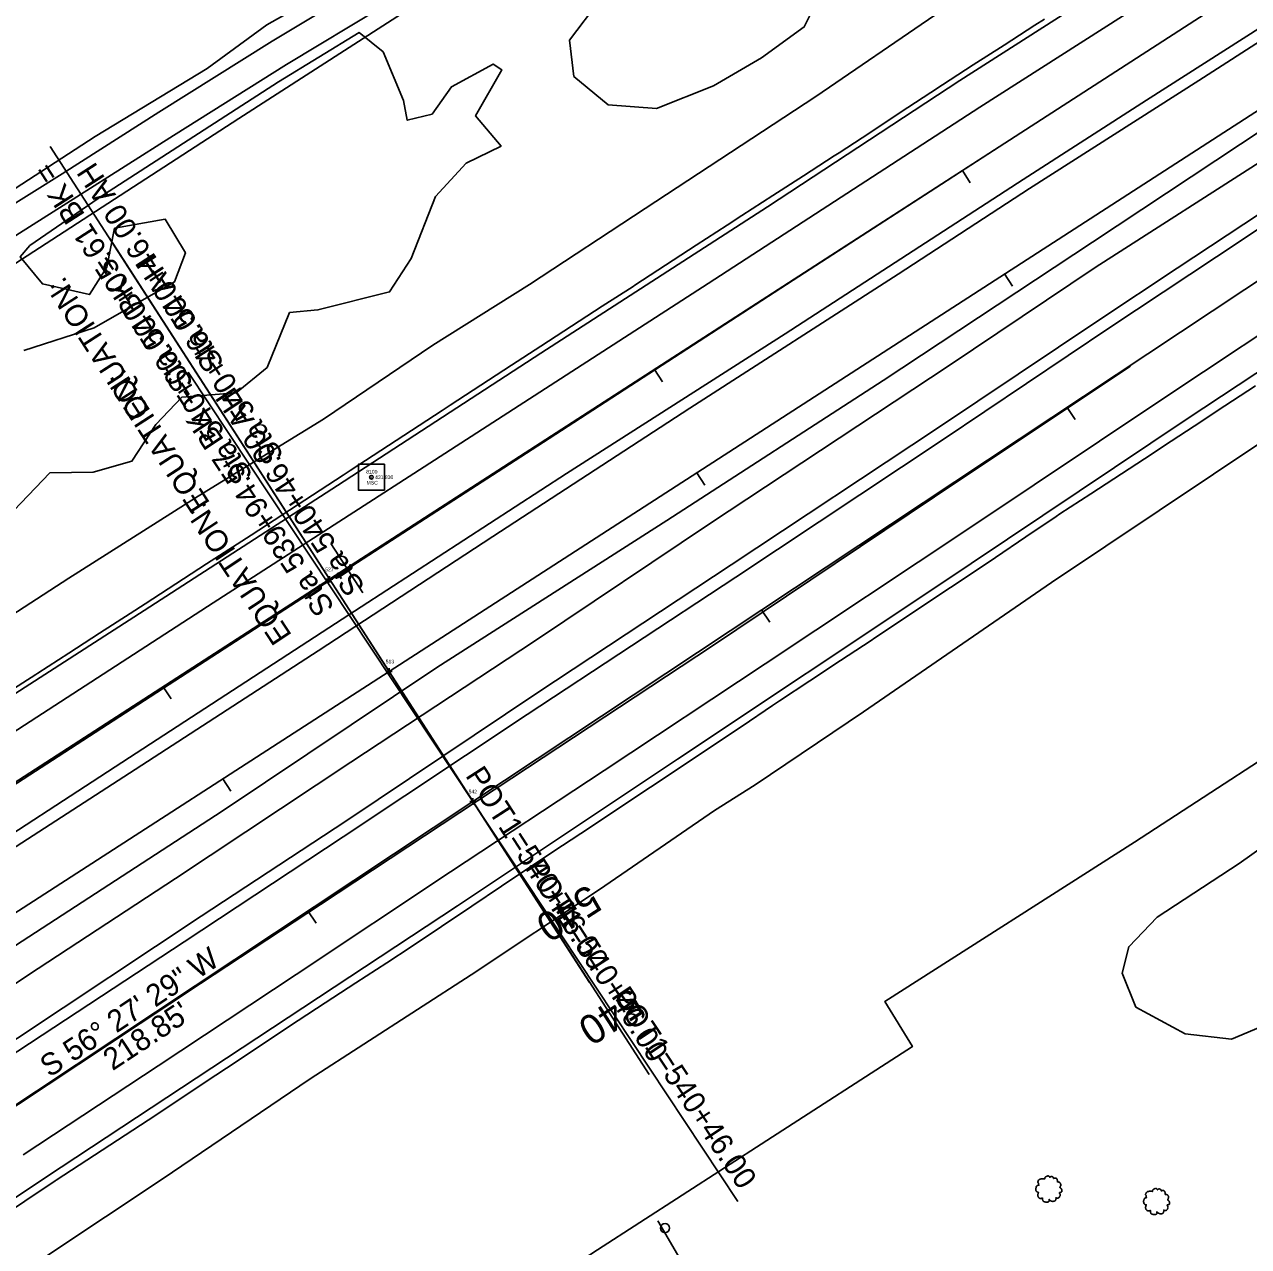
# Model space of a CAD drawing. Extents: x 1901471 to 1963503, y 756461 to 799997.
# Drawn here: x 1926646.3 to 1926980.4, y 771313.9 to 771647.3 of the extents above; entities that cross this region are included whole.
import ezdxf

# ---------------------------------------------------------------- set-up
doc = ezdxf.new("R2010")
doc.units = 0
for name, color, linetype in [('Default', 7, 'Continuous'), ('RD_DTM_BkLn1', 7, 'Continuous'), ('RD_EX_Bldg', 7, 'Continuous'), ('RD_EX_Conc', 7, 'Continuous'), ('RD_EX_Fence_Other', 7, 'Continuous'), ('RD_EX_H2O', 7, 'Continuous'), ('RD_EX_Road', 7, 'Continuous'), ('RD_EX_Road_txCode', 7, 'Continuous'), ('RD_EX_VEG', 7, 'Continuous'), ('RD_HC_Cl', 7, 'Continuous'), ('RD_HC_Data', 7, 'Continuous'), ('RD_HC_Data_Tic', 7, 'Continuous'), ('RD_HC_Survey', 7, 'Continuous'), ('RD_HC_TX_Sta50', 7, 'Continuous'), ('RD_HC_txCode', 7, 'Continuous'), ('RD_SMD_Locator', 7, 'Continuous')]:
    doc.layers.add(name, color=color, linetype=linetype)

# ---------------------------------------------------------------- blocks, each defined once
blk = doc.blocks.new('T2')
at = {"layer": 'RD_EX_VEG'}
for points in [[(0.05, 7.21), (-0.25, 7.24), (-0.57, 7.14), (-0.82, 7.04), (-1.05, 6.96), (-1.27, 6.86), (-1.57, 6.69), (-1.8, 6.49), (-1.92, 6.24), (-1.97, 6.01), (-2.02, 5.74), (-2.02, 5.56), (-2.15, 5.54), (-2.3, 5.56), (-2.55, 5.64), (-2.8, 5.64), (-3.05, 5.64), (-3.4, 5.61), (-3.75, 5.61), (-4.02, 5.56), (-4.35, 5.51), (-4.72, 5.39), (-5.07, 5.26), (-5.37, 5.01), (-5.62, 4.54), (-5.75, 4.19), (-5.9, 3.94), (-5.75, 3.49), (-5.57, 3.14), (-5.55, 2.94), (-5.47, 2.52), (-5.37, 2.29), (-5.25, 2.09), (-5.32, 2.07), (-5.7, 2.02), (-6, 1.92), (-6.42, 1.69), (-6.64, 1.47), (-6.74, 1.14), (-6.77, 0.79), (-6.87, 0.59), (-6.94, 0.32), (-6.97, 0.24), (-7.02, -0.08), (-6.92, -0.53), (-6.89, -0.88), (-6.77, -1.11), (-6.62, -1.28), (-6.44, -1.53), (-6.05, -1.76), (-5.72, -1.86), (-5.52, -1.88), (-5.7, -2.38), (-5.75, -2.73), (-5.87, -3.13), (-5.87, -3.21), (-5.92, -3.68), (-5.77, -4.01), (-5.7, -4.38), (-5.52, -4.61), (-5.25, -4.91), (-4.92, -5.13), (-4.42, -5.26), (-4.02, -5.23), (-3.45, -5.06), (-3.2, -4.98), (-3.22, -5.16), (-3.2, -5.53), (-3.2, -5.96), (-3.05, -6.28), (-2.95, -6.56), (-2.8, -6.81), (-2.47, -7.03), (-2.07, -7.11), (-1.65, -7.26), (-1.2, -7.33), (-0.7, -7.36), (-0.1, -7.21), (0.18, -7.08), (0.28, -6.91), (0.48, -6.53), (0.43, -6.31), (0.45, -5.71), (0.55, -5.88), (0.73, -6.23), (1.23, -6.53), (1.63, -6.71), (2.1, -6.86), (2.4, -6.93), (2.88, -6.86), (3.25, -6.78), (3.63, -6.66), (3.93, -6.38), (4.1, -6.11), (4.15, -5.83), (4.23, -5.46), (4.28, -5.28)], [(4.28, -5.28), (4.2, -5.11), (4.15, -4.86), (4.23, -4.88), (4.4, -4.93), (4.68, -5.06), (4.9, -5.13), (5.23, -5.11), (5.5, -5.01), (5.95, -4.73), (6.22, -4.26), (6.5, -3.86), (6.57, -3.53), (6.52, -3.31), (6.5, -2.81), (6.3, -2.56), (6.25, -2.43), (6.15, -2.03), (6.22, -1.98), (6.5, -1.93), (6.87, -1.81), (7.15, -1.68), (7.37, -1.51), (7.45, -1.28), (7.42, -0.88), (7.47, -0.48), (7.4, -0.33), (7.3, -0.18), (7.22, 0.02), (7.07, 0.17), (6.97, 0.32), (6.87, 0.42), (6.75, 0.57), (6.57, 0.69), (6.42, 0.74), (6.37, 0.89), (6.52, 1.09), (6.57, 1.19), (6.6, 1.42), (6.82, 1.77), (6.87, 2.17), (6.82, 2.59), (6.77, 2.87), (6.62, 3.14), (6.42, 3.39), (6.3, 3.56), (6.12, 3.69), (5.8, 3.81), (5.55, 3.86), (5.2, 3.86), (5, 3.91), (5.03, 3.96), (5.03, 4.11), (5.03, 4.39), (4.95, 4.84), (4.8, 5.34), (4.8, 5.36), (4.7, 5.61), (4.48, 5.81), (4.3, 5.91), (4.1, 6.04), (3.85, 6.06), (3.55, 6.06), (3.28, 6.01), (3.08, 5.91), (2.9, 5.79), (2.83, 5.94), (2.73, 6.24), (2.68, 6.39), (2.53, 6.56), (2.3, 6.76), (1.85, 6.89), (1.23, 6.81), (0.93, 6.61), (0.78, 6.44), (0.73, 6.56), (0.53, 6.76), (0.43, 6.94), (0.25, 7.06), (0.1, 7.16), (0, 7.21)]]:
    blk.add_spline(points, degree=3, dxfattribs=at)
blk = doc.blocks.new('SIGNPOST')
at = {"layer": 'Default'}
for start, end in [(90, 270), (270, 90)]:
    blk.add_arc((0, 0), 0.127, start, end, dxfattribs=at)

msp = doc.modelspace()

# ---------------------------------------------------------------- linework, layer by layer
at = {"layer": 'Default'}
for p, q in [((1926730.39, 771495.93), (1926728.64, 771495.93)), ((1926729.52, 771496.8), (1926729.52, 771495.05)), ((1926746.63, 771470.78), (1926744.88, 771470.78)), ((1926745.76, 771471.65), (1926745.76, 771469.9)), ((1926768.65, 771436.19), (1926768.65, 771434.44)), ((1926769.53, 771435.31), (1926767.78, 771435.31))]:
    msp.add_line(p, q, dxfattribs=at)
at = {"layer": 'RD_DTM_BkLn1'}
for points in [[(1926640.96, 771464.62), (1926649.39, 771470), (1926649.94, 771470.36), (1926658.34, 771475.78), (1926666.75, 771481.2), (1926675.15, 771486.63), (1926679.18, 771489.23), (1926687.57, 771494.67), (1926695.96, 771500.12), (1926704.35, 771505.56), (1926708.14, 771508.01), (1926716.52, 771513.47), (1926724.9, 771518.92), (1926733.28, 771524.38), (1926735.15, 771525.59), (1926743.51, 771531.07), (1926751.88, 771536.54), (1926760.25, 771542.01), (1926762.42, 771543.43), (1926770.81, 771548.88), (1926779.19, 771554.33), (1926787.19, 771559.53), (1926795.58, 771564.98), (1926803.97, 771570.42), (1926812.36, 771575.86), (1926812.87, 771576.19), (1926821.26, 771581.64), (1926829.64, 771587.09), (1926838.02, 771592.54), (1926842.08, 771595.18), (1926850.49, 771600.6), (1926858.9, 771606.01), (1926867.3, 771611.43), (1926868.62, 771612.27), (1926876.97, 771617.78), (1926885.32, 771623.28), (1926893.67, 771628.78), (1926896.82, 771630.86), (1926905.23, 771636.27), (1926913.64, 771641.68), (1926922.05, 771647.09), (1926924.7, 771648.79)], [(1926638.05, 771320.73), (1926646.36, 771326.29), (1926654.67, 771331.85), (1926654.93, 771332.03), (1926663.31, 771337.49), (1926671.68, 771342.96), (1926680.06, 771348.42), (1926681.8, 771349.56), (1926690.13, 771355.09), (1926698.45, 771360.63), (1926704.29, 771364.5), (1926712.63, 771370.02), (1926720.97, 771375.53), (1926728.35, 771380.4), (1926736.74, 771385.85), (1926745.13, 771391.3), (1926751.8, 771395.63), (1926760.1, 771401.21), (1926768.41, 771406.78), (1926776.45, 771412.18), (1926784.77, 771417.72), (1926793.09, 771423.27), (1926800.45, 771428.17), (1926808.79, 771433.69), (1926817.13, 771439.22), (1926825.51, 771444.77), (1926833.82, 771450.34), (1926842.12, 771455.91), (1926850.43, 771461.48), (1926852.31, 771462.74), (1926860.65, 771468.25), (1926868.99, 771473.76), (1926877.34, 771479.28), (1926878.4, 771479.98), (1926886.73, 771485.51), (1926895.06, 771491.04), (1926903, 771496.32), (1926911.29, 771501.91), (1926919.59, 771507.5), (1926927.88, 771513.09), (1926928.9, 771513.78), (1926937.28, 771519.24), (1926945.66, 771524.7), (1926954.04, 771530.16), (1926957.2, 771532.22), (1926965.54, 771537.73), (1926973.89, 771543.24), (1926982.23, 771548.75)]]:
    msp.add_lwpolyline(points, dxfattribs=at)
at = {"layer": 'RD_EX_Bldg'}
msp.add_lwpolyline([(1926819.14, 771320.9), (1926843.13, 771279.78)], dxfattribs=at)
at = {"layer": 'RD_EX_Conc'}
for points in [[(1926913.86, 771614.96), (1926856.12, 771577.52), (1926789.49, 771534.35), (1926717.34, 771487.72), (1926653.86, 771446.58), (1926587.5, 771403.7), (1926520.58, 771360.56), (1926450.82, 771315.78), (1926386.48, 771274.03), (1926337.64, 771242.68)], [(1926948.19, 771554.09), (1926901.28, 771522.85), (1926834.08, 771477.82), (1926779.24, 771441.71), (1926727.03, 771407.22), (1926694.32, 771385.69), (1926636.12, 771347.16), (1926575.7, 771307.03), (1926508.61, 771262.66), (1926440.97, 771217.97), (1926376.41, 771175.44)]]:
    msp.add_lwpolyline(points, dxfattribs=at)
at = {"layer": 'RD_EX_Fence_Other'}
for points in [[(1926123.55, 771248.7), (1926275.46, 771344.86), (1926355.52, 771395.91), (1926424.79, 771441.17), (1926530.89, 771509.43), (1926628.27, 771572.09), (1926704.79, 771621.63), (1926787.18, 771674.72), (1926849.91, 771715.16), (1926941.17, 771774.91), (1927014.76, 771822.08), (1927102.81, 771879.34), (1927189.76, 771936.16), (1927324.36, 772022.72), (1927401.87, 772072.57), (1927505.46, 772139.07), (1927552.57, 772169.38), (1927610.42, 772206.83), (1927669.56, 772245.41), (1927727.77, 772282), (1927850.35, 772361.69), (1927906.61, 772393.18), (1928159.93, 772541.58)], [(1926182.3, 771080.62), (1926247.6, 771123.86), (1926313.93, 771167.94), (1926371.02, 771205.25), (1926416.83, 771235.47), (1926477.89, 771275.65), (1926522.02, 771304.72), (1926569.04, 771335.92), (1926611.21, 771363.72), (1926647.32, 771388), (1926687.51, 771414.32), (1926735.3, 771446.06), (1926785.74, 771479.26), (1926833.51, 771511.22), (1926898.65, 771554.27), (1926938.55, 771580.97), (1926986.82, 771611.93), (1927022.76, 771635.27), (1927060.7, 771659.72), (1927104.19, 771687.49), (1927151.86, 771719.24), (1927193.2, 771746.24), (1927158.07, 771727.8)], [(1927228.56, 771605.61), (1927165.98, 771565.13), (1927099.93, 771522.87), (1927038.81, 771482.69), (1927005.75, 771461), (1926949.23, 771424.25), (1926881.07, 771380.73), (1926888.61, 771368.43), (1926848.87, 771342.84), (1926802.71, 771313), (1926719.32, 771258.75), (1926644.18, 771208.93), (1926569.77, 771160.02), (1926501.11, 771115.2), (1926445.81, 771078.5), (1926373.01, 771031.13), (1926312.17, 770989.89), (1926284.96, 770971.08)]]:
    msp.add_lwpolyline(points, dxfattribs=at)
at = {"layer": 'RD_EX_H2O'}
for points in [[(1926621.74, 771472.5), (1926658.38, 771496.29), (1926693.65, 771518.59), (1926727.86, 771539.59), (1926757.76, 771559.85), (1926784.12, 771576.35), (1926815.7, 771597.13), (1926862.25, 771627.63), (1926894.71, 771649.8), (1926905.89, 771656.34), (1926923.69, 771667.88), (1926953.22, 771687.95), (1926979.12, 771704.75), (1927005.16, 771721.72), (1927025.82, 771736.39), (1927046.28, 771750.15), (1927056.44, 771759.51)], [(1927178.55, 771746.03), (1927142.04, 771722.6), (1927087.07, 771685.87), (1927035.71, 771652.42), (1926984.95, 771619.06), (1926937.79, 771587.95), (1926880.68, 771550.21), (1926821.56, 771511.96), (1926758.84, 771471.9), (1926700.21, 771432.66), (1926643.77, 771396.01), (1926572.34, 771349.32), (1926498.61, 771301.78), (1926441.76, 771263.88), (1926366.72, 771215.15), (1926345.97, 771201.99), (1926308.41, 771177.14), (1926262.44, 771147.1)], [(1926411.81, 771116.97), (1926438.8, 771138.98), (1926480.42, 771170.67), (1926521.51, 771204.87), (1926537.81, 771219.83), (1926569.72, 771245.95), (1926601.52, 771273.26), (1926624.78, 771291.39), (1926652.88, 771311.72), (1926683.86, 771332.27), (1926724.26, 771359.64), (1926768.21, 771388), (1926803.18, 771411.27), (1926834.57, 771432.84), (1926845.7, 771439.87), (1926875.28, 771459.74), (1926926.55, 771495.04), (1926970.79, 771524.6), (1927006.19, 771548.26), (1927043.02, 771572.6), (1927072.89, 771592.2), (1927106.12, 771613.29), (1927137.2, 771633.31), (1927158.83, 771647.13)]]:
    msp.add_lwpolyline(points, dxfattribs=at)
at = {"layer": 'RD_EX_Road'}
for points in [[(1927002.69, 771834.44), (1926969.23, 771813.34), (1926939.87, 771793.11), (1926911.84, 771773.82), (1926879.83, 771751.75), (1926845.39, 771727.24), (1926813.48, 771704.98), (1926791.52, 771689.64), (1926764.88, 771673.54), (1926740.22, 771658.67), (1926713.82, 771642.74), (1926682.97, 771623.37), (1926656.55, 771606.59), (1926631.63, 771590.96)], [(1927006.64, 771828.07), (1926973.36, 771807.08), (1926944.13, 771786.94), (1926916.09, 771767.64), (1926884.14, 771745.61), (1926849.71, 771721.11), (1926817.77, 771698.83), (1926795.61, 771683.35), (1926768.75, 771667.11), (1926744.09, 771652.25), (1926717.75, 771636.36), (1926686.97, 771617.03), (1926660.56, 771600.25), (1926635.58, 771584.58)], [(1927167.58, 771805.44), (1927132.53, 771782.19), (1927125.25, 771776.81), (1927087.59, 771752.02), (1927053.76, 771729.63), (1927035.3, 771718.19), (1927013.38, 771703.59), (1926986.15, 771685.9), (1926961.73, 771670.26), (1926935.01, 771653.41), (1926901.57, 771632.05), (1926849.07, 771597.53), (1926787.19, 771557.66), (1926731.73, 771521.52), (1926678.93, 771487.39), (1926612.37, 771444.56), (1926561.87, 771411.9), (1926510.4, 771379.07), (1926470.49, 771353.37), (1926426.89, 771325.32), (1926388.11, 771299.87), (1926326.45, 771259.81), (1926252.5, 771212.2), (1926204.25, 771180.69)], [(1927149.35, 771780.93), (1927120.56, 771762.29), (1927086.84, 771740.15), (1927051.47, 771717.13), (1927018.6, 771696.09), (1926983.47, 771673.66), (1926945.99, 771649.59), (1926906.99, 771624.78), (1926832.84, 771576.62), (1926755.38, 771526.66), (1926697.72, 771489.54), (1926627.78, 771444.21), (1926557.1, 771398.6), (1926503.29, 771363.85), (1926451.94, 771330.76), (1926402.89, 771299.02), (1926358.62, 771270.33), (1926331.71, 771252.84), (1926280.14, 771219.61), (1926220.65, 771181.12), (1926155.39, 771139.06)], [(1926198.04, 771135.51), (1926265.67, 771178.91), (1926344.33, 771229.73), (1926401.98, 771266.94), (1926443.51, 771293.54), (1926486.5, 771321.44), (1926535.14, 771352.78), (1926585.38, 771385.13), (1926623.75, 771410.05), (1926674.88, 771443.08), (1926726.38, 771476.39), (1926774.06, 771507.6), (1926827.87, 771542.61), (1926884.73, 771579.17), (1926920.56, 771602.59), (1926966.82, 771632), (1927005.55, 771657.03), (1927044.01, 771681.86), (1927078.23, 771703.97), (1927115.16, 771727.46), (1927145.35, 771747.05), (1927181.66, 771770.5)], [(1926173.64, 771123.8), (1926231.16, 771160.73), (1926288.05, 771197.26), (1926342.13, 771232.32), (1926407.18, 771274.33), (1926447.65, 771300.57), (1926497.51, 771332.92), (1926539.88, 771360.11), (1926583.3, 771388.17), (1926626.5, 771415.87), (1926674.88, 771447.29), (1926731.15, 771483.92), (1926794.25, 771524.81), (1926853.92, 771562.89), (1926918.89, 771605.02), (1926952.49, 771626.65), (1926984.15, 771646.87), (1927014.02, 771666.12), (1927045.33, 771686.54), (1927084.81, 771711.89), (1927125.73, 771738.37), (1927158.39, 771759.31)], [(1926170.56, 771054.37), (1926238.93, 771099.25), (1926310, 771145.81), (1926373.26, 771187.27), (1926415.21, 771215.09), (1926455.3, 771241.66), (1926509.67, 771277.66), (1926551.63, 771305.6), (1926597.02, 771335.88), (1926641.29, 771365.08), (1926689.8, 771397.01), (1926733.2, 771425.68), (1926783.44, 771459.04), (1926840.44, 771496.53), (1926897.05, 771534.1), (1926942.53, 771564.64), (1926971.64, 771583.88), (1927009.1, 771608.79), (1927048.55, 771634.86), (1927086.14, 771659.77), (1927129.55, 771688.23), (1927165.58, 771711.85)], [(1926176.79, 771062.24), (1926235.35, 771100.84), (1926300.5, 771143.98), (1926370.87, 771190.2), (1926404.8, 771212.49), (1926455.53, 771246.01), (1926503.18, 771277.65), (1926550.65, 771309.1), (1926596.81, 771339.51), (1926644.32, 771370.78), (1926694.49, 771404), (1926733.97, 771429.97), (1926786.39, 771465.06), (1926839.15, 771499.87), (1926895.5, 771537.14), (1926939.55, 771566.67), (1926960.91, 771580.78), (1926992.74, 771601.8), (1927022.16, 771621.57), (1927056.83, 771644.53), (1927087.63, 771664.63), (1927123.94, 771688.69), (1927155.05, 771708.6)], [(1927170.27, 771686.84), (1927142.87, 771668.65), (1927116.24, 771650.81), (1927089.47, 771633.11), (1927058.66, 771612.65), (1927025.87, 771590.97), (1927000.02, 771573.77), (1926957.5, 771545.57), (1926904.03, 771509.75), (1926848.47, 771472.87), (1926804.49, 771443.81), (1926762.52, 771416.09), (1926720.43, 771388.11), (1926682.72, 771363.2), (1926645.94, 771338.94)], [(1927152.94, 771664.86), (1927101.09, 771630.75), (1927052.06, 771598.27), (1927006.18, 771567.84), (1926963.36, 771539.5), (1926895, 771493.75), (1926824.53, 771446.86), (1926764.43, 771406.89), (1926709.7, 771370.74), (1926656.24, 771335.58), (1926607.89, 771303.47), (1926565.17, 771275.17), (1926515.99, 771242.67), (1926463.66, 771208.1), (1926387.37, 771157.95), (1926296.97, 771098.58), (1926223, 771049.97), (1926143.15, 770997.31)], [(1927007.96, 771366.62), (1927002.58, 771375.32), (1926992.38, 771377.44), (1926975.75, 771370.48), (1926963.06, 771371.91), (1926949.6, 771379.21), (1926945.89, 771388.51), (1926947.69, 771395.69), (1926955.43, 771403.79), (1926977.77, 771418.4), (1927006.13, 771438.48), (1927017.97, 771447.97), (1927033.86, 771459.94), (1927051.63, 771475.47), (1927090.21, 771498.28), (1927120.92, 771517.76), (1927142.63, 771534.23), (1927164.09, 771543.85)]]:
    msp.add_lwpolyline(points, dxfattribs=at)
at = {"layer": 'RD_EX_VEG'}
for points in [[(1926980.16, 771824.83), (1926956.57, 771809.59), (1926931.92, 771790.56), (1926888.59, 771761.67), (1926869.92, 771749.57), (1926854.61, 771738.23), (1926841.33, 771729.4), (1926803.7, 771702.53), (1926772.13, 771684.02), (1926743.31, 771664.65), (1926712.37, 771647.22), (1926696.08, 771635.29), (1926665.52, 771616.78), (1926640.1, 771600.15)], [(1926863.97, 771656.55), (1926859.11, 771646.63), (1926847.39, 771638.21), (1926834.31, 771630.58), (1926818.79, 771624.35), (1926805.55, 771625.34), (1926796.22, 771633.11), (1926795.02, 771643.05), (1926803.3, 771653.89)], [(1926646.05, 771558.39), (1926665.29, 771564.56), (1926687.25, 771577.05), (1926690.19, 771585.04), (1926684.68, 771594.15), (1926670.84, 771591.72), (1926668.78, 771581.13), (1926664.01, 771573.61), (1926651.17, 771576.54), (1926645.1, 771583.94), (1926647.76, 771587.04), (1926667.85, 771600.82), (1926715.59, 771631.69), (1926737.63, 771645.07), (1926744.13, 771639.8), (1926749.7, 771626.54), (1926750.73, 771621.17), (1926757.53, 771622.81), (1926762.81, 771630.33), (1926774.17, 771636.49), (1926776.57, 771634.89), (1926769.38, 771622.41), (1926776.37, 771614.11), (1926776.37, 771614.11), (1926766.84, 771609.49), (1926758.41, 771600.4), (1926751.82, 771583.46), (1926745.91, 771574.36), (1926726.35, 771569.42), (1926718.62, 771568.68), (1926712.54, 771553.75), (1926704.05, 771546.8), (1926689.25, 771545.58), (1926682.07, 771538.15), (1926675.58, 771528.16), (1926664.97, 771525.18), (1926653.19, 771524.98), (1926643.35, 771514.72)]]:
    msp.add_lwpolyline(points, dxfattribs=at)
at = {"layer": 'RD_HC_Cl'}
for p, q in [((1927706.19, 772126.46), (1926729.52, 771495.93)), ((1927726.32, 772103.83), (1926745.76, 771470.78)), ((1927625.44, 772003.31), (1926768.65, 771435.31)), ((1926729.52, 771495.93), (1917217.27, 765354.92)), ((1926745.76, 771470.78), (1917232.23, 765328.83)), ((1926768.65, 771435.31), (1926586.25, 771314.39))]:
    msp.add_line(p, q, dxfattribs=at)
at = {"layer": 'RD_HC_Data'}
for p, q in [((1926729.52, 771495.93), (1926653.28, 771614.02)), ((1926745.76, 771470.78), (1926669.52, 771588.87)), ((1926768.65, 771435.31), (1926690.98, 771552.47)), ((1926729.52, 771495.93), (1926800.51, 771385.96)), ((1926745.76, 771470.78), (1926816.75, 771360.81)), ((1926768.65, 771435.31), (1926840.98, 771326.21))]:
    msp.add_line(p, q, dxfattribs=at)
at = {"layer": 'RD_HC_Data_Tic'}
for p, q in [((1926902.26, 771607.45), (1926904.43, 771604.09)), ((1926913.78, 771579.25), (1926915.95, 771575.89)), ((1926818.24, 771553.21), (1926820.41, 771549.85)), ((1926930.82, 771542.82), (1926933.03, 771539.49)), ((1926829.77, 771525.02), (1926831.94, 771521.65)), ((1926734.23, 771498.97), (1926729.89, 771505.69)), ((1926734.23, 771498.97), (1926738.57, 771492.25)), ((1926847.47, 771487.57), (1926849.68, 771484.23)), ((1926745.76, 771470.78), (1926741.42, 771477.5)), ((1926745.76, 771470.78), (1926750.1, 771464.06)), ((1926684.15, 771466.64), (1926686.32, 771463.28)), ((1926700.39, 771441.49), (1926702.56, 771438.13)), ((1926723.64, 771405.47), (1926725.85, 771402.14))]:
    msp.add_line(p, q, dxfattribs=at)
at = {"layer": 'RD_HC_Survey'}
msp.add_lwpolyline([(1926744.49, 771527.33), (1926737.42, 771527.33), (1926737.42, 771520.26), (1926744.49, 771520.26)], close=True, dxfattribs=at)
msp.add_circle((1926740.95, 771523.79), 0.5, dxfattribs=at)
at = {"layer": 'RD_SMD_Locator'}
msp.add_circle((1926740.95, 771523.79), 0.001, dxfattribs=at)

# ---------------------------------------------------------------- block references
at = {"layer": 'RD_EX_Bldg', "xscale": 9.84251968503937, "yscale": 9.84251968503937}
msp.add_blockref('SIGNPOST', (1926821.11, 771318.93), dxfattribs=at)
at = {"layer": 'RD_EX_VEG', "xscale": 0.4921259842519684, "yscale": 0.4921259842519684}
for p in [(1926925.74, 771329.61), (1926955.16, 771326.22)]:
    msp.add_blockref('T2', p, dxfattribs=at)

# ---------------------------------------------------------------- texts
at = {"layer": 'Default'}
for s, p in [('527', (1926728.34, 771498.13)), ('513', (1926744.86, 771472.98)), ('542', (1926767.47, 771437.51))]:
    msp.add_text(s, height=1, dxfattribs=at).set_placement(p)
at = {"layer": 'RD_EX_Road_txCode'}
msp.add_text('431.830', height=1, dxfattribs=at).set_placement((1926741.95, 771523.29))
at = {"layer": 'RD_HC_Data'}
for s, rotation, p in [('Sta 540+46.00 AH', 122.8459, (1926700.98, 771554.88)), ('Sta 540+05.61 BK = ', 122.8459, (1926692.58, 771549.45)), ('Sta 540+00.00 BK = ', 122.8464, (1926708.82, 771524.3)), ('Sta 540+46.00 AH', 122.8464, (1926717.22, 771529.72)), ('EQUATION:', 122.8459, (1926680.82, 771541.86)), ('EQUATION:', 122.8464, (1926697.06, 771516.71)), ('Sta 539+94.57 BK = ', 123.5419, (1926731.07, 771488.38)), ('Sta 540+46.00 AH', 123.5419, (1926739.4, 771493.91)), ('EQUATION:', 123.5419, (1926719.4, 771480.65)), ('POT1=540+46.00', 302.8459, (1926766.45, 771442.4)), ('POT1=540+46.00', 302.8464, (1926782.69, 771417.25)), ('S 56%%d 27\' 29" W', 33.5419, (1926653.07, 771359.89)), ('POT1=540+46.00', 303.5419, (1926806.23, 771382.24)), ("218.85'", 33.5419, (1926670.3, 771361.71))]:
    msp.add_text(s, height=6, rotation=rotation, dxfattribs=at).set_placement(p)
at = {"layer": 'RD_HC_TX_Sta50'}
for rotation, p in [(212.8459, (1926800.15, 771412.97)), (212.8464, (1926811.67, 771384.78))]:
    msp.add_text('540', height=8, rotation=rotation, dxfattribs=at).set_placement(p)
at = {"layer": 'RD_HC_txCode'}
for s, p in [('8100', (1926739.53, 771524.79)), ('MSC', (1926739.64, 771521.79))]:
    msp.add_text(s, height=1, dxfattribs=at).set_placement(p)

doc.saveas('drawing.dxf')
